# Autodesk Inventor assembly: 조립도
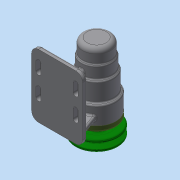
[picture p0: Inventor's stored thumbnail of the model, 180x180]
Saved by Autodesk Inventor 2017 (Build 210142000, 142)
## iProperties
Part Number: 조립도
Material: 일반
Document SubType Name: Assembly
Designer: MRC
Author: MRC
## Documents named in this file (12)
- C:\Users\MRC\Desktop\711009V1004\조립도.iam
- C:\Users\MRC\Desktop\711009V1004\본체.ipt
- C:\Users\MRC\Desktop\711009V1004\V벨트풀리.ipt
- C:\Users\MRC\Desktop\711009V1004\멈춤나사 M3.ipt
- C:\Users\MRC\Desktop\711009V1004\베어링 6004.ipt
- C:\Users\MRC\Desktop\711009V1004\베어링 51202.ipt
- C:\Users\MRC\Desktop\711009V1004\볼트 M4.ipt
- C:\Users\MRC\Desktop\711009V1004\어댑터슬리브.ipt
- C:\Users\MRC\Desktop\711009V1004\오일 실 20x35x7.ipt
- C:\Users\MRC\Desktop\711009V1004\축.ipt
- C:\Users\MRC\Desktop\711009V1004\커버.ipt
- C:\Users\MRC\Desktop\711009V1004\키 5x5.ipt
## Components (1 placed, 1 different names)
1. V벨트풀리:1
